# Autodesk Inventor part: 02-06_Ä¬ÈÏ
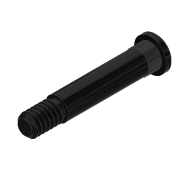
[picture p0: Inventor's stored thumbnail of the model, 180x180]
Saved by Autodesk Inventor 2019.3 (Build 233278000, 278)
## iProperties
Created: 2010-06
Part Number: 02-06_Ä¬ÈÏ
Material: Ogólny
Document SubType Name: Modeling
Designer: CADENGINEERING4
Density: 1 g/cm^3
Appearance: Gładki — czarny
Author: CADENGINEERING4
Revision Number: ÈÎºÎ
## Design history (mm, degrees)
feature "NONE"
node "Bryła1"
